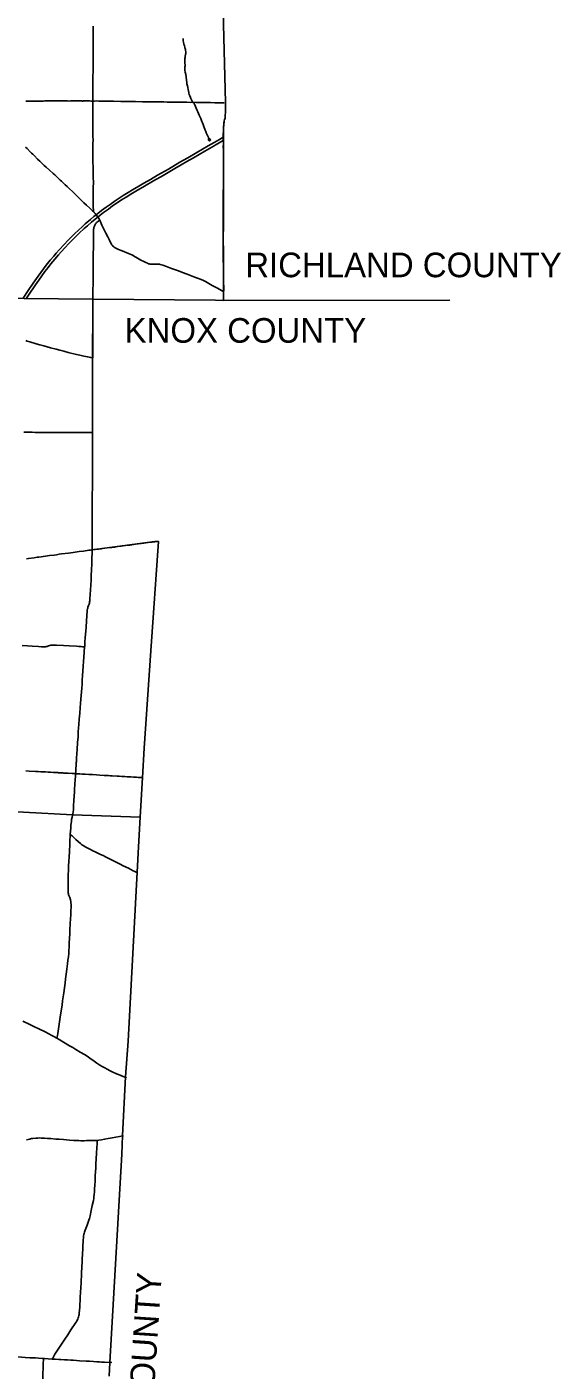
# Model space of a CAD drawing. Extents: x 1815539 to 1947826, y 273303 to 993194.
# Drawn here: x 1926135 to 1947826, y 885394 to 939932 of the extents above; entities that cross this region are included whole.
import ezdxf

# ---------------------------------------------------------------- set-up
doc = ezdxf.new("R2010")
doc.units = 0
for name, color, linetype in [('GM_X_Adjacent_County_Text', 7, 'Continuous'), ('GM_X_County', 7, 'Continuous'), ('GM_X_County_Road', 7, 'Continuous'), ('GM_X_Interstate_Route', 7, 'Continuous'), ('GM_X_State_Route', 7, 'Continuous'), ('GM_X_Township', 7, 'Continuous'), ('GM_X_Township_Road', 7, 'Continuous'), ('PV_X_EOP', 7, 'Continuous')]:
    doc.layers.add(name, color=color, linetype=linetype)

msp = doc.modelspace()

# ---------------------------------------------------------------- linework, layer by layer
at = {"layer": 'GM_X_County'}
msp.add_lwpolyline([(1934067, 942157), (1934195, 936859), (1934202, 936590), (1934187, 936214), (1934165, 936177), (1934141, 936112), (1934134, 936040), (1934113, 935746), (1934115, 935394), (1934114, 935137), (1934107, 931513), (1934121, 929197), (1934122, 928828), (1933789, 928831), (1928810, 928882), (1928810, 928443), (1928806, 926508), (1928802, 923466), (1928787, 918701), (1931337, 919032), (1931473, 919044), (1931168, 914595), (1930891, 910644), (1930824, 909461), (1930733, 907844), (1930665, 906634), (1930611, 905616), (1930247, 898751), (1930144, 897297), (1930019, 894924), (1929994, 894165), (1929509, 885709), (1929483, 885147)], dxfattribs=at)
at = {"layer": 'GM_X_County_Road'}
for points in [[(1928857, 932416), (1928853, 932423), (1928846, 932439), (1928840, 932455), (1928837, 932472), (1928834, 932505), (1928831, 932603), (1928831, 932686), (1928832, 932784), (1928829, 932882), (1928822, 933046), (1928822, 933128), (1928824, 933211), (1928828, 933342), (1928829, 933406), (1928834, 933615), (1928835, 933681), (1928833, 933763), (1928824, 933910), (1928824, 933976), (1928824, 934058), (1928826, 934156), (1928824, 934287), (1928820, 934402), (1928819, 934517), (1928816, 934697), (1928816, 934798), (1928818, 934944), (1928818, 935027), (1928819, 935173), (1928821, 935370), (1928820, 935452), (1928817, 935615), (1928816, 935697), (1928816, 935812), (1928817, 935878), (1928818, 935927), (1928816, 936057), (1928817, 936106), (1928815, 936187), (1928814, 936253), (1928815, 936338), (1928814, 936398), (1928814, 936484), (1928814, 936548), (1928813, 936617), (1928815, 936711), (1928813, 936793), (1928811, 936857), (1928812, 936921)], [(1928817, 928861), (1928819, 929108), (1928819, 929239), (1928821, 929519), (1928823, 929666), (1928824, 929814), (1928825, 929978), (1928826, 930076), (1928827, 930158), (1928827, 930289), (1928828, 930437), (1928830, 930617), (1928832, 930781), (1928834, 930912), (1928835, 931043), (1928837, 931207), (1928836, 931372), (1928836, 931470), (1928838, 931602), (1928841, 931667), (1928845, 931717), (1928849, 931750), (1928856, 931782), (1928865, 931814), (1928877, 931845), (1928890, 931875), (1928907, 931904), (1928926, 931932), (1928946, 931958), (1928968, 931983), (1928992, 932006), (1929016, 932028), (1929041, 932048), (1929055, 932059), (1929067, 932068), (1929077, 932076), (1929084, 932092)], [(1929084, 932092), (1929079, 932103), (1929073, 932118), (1929066, 932132), (1929040, 932173), (1929014, 932209), (1929002, 932227), (1928946, 932299), (1928902, 932357), (1928871, 932395), (1928861, 932409), (1928857, 932416)], [(1928807, 926493), (1928809, 926621), (1928809, 926752), (1928812, 926899), (1928813, 926997), (1928812, 927177), (1928812, 927324), (1928811, 927487), (1928811, 927749), (1928813, 927847), (1928813, 928059), (1928812, 928190), (1928814, 928353), (1928815, 928468), (1928815, 928598), (1928816, 928761), (1928817, 928861)], [(1926090, 927194), (1926151, 927172), (1926261, 927138), (1926513, 927065), (1926655, 927025), (1926829, 926978), (1926956, 926945), (1927098, 926906), (1927320, 926845), (1927478, 926804), (1927637, 926763), (1927811, 926716), (1928145, 926630), (1928289, 926597), (1928449, 926564), (1928610, 926534), (1928723, 926513), (1928807, 926493)], [(1928786, 918696), (1928859, 918706), (1928908, 918712), (1928973, 918721), (1929054, 918732), (1929151, 918744), (1929199, 918750), (1929489, 918787), (1929586, 918799), (1929700, 918813), (1929814, 918828), (1929960, 918847), (1930139, 918870), (1930317, 918893), (1930545, 918924), (1930886, 918970), (1931065, 918992), (1931227, 919011), (1931335, 919024)], [(1931335, 919024), (1931443, 919037)], [(1926118, 918334), (1926198, 918346), (1926425, 918377), (1926555, 918395), (1926620, 918404), (1926896, 918441), (1927059, 918463), (1927237, 918487), (1927335, 918501), (1927448, 918517), (1927546, 918531), (1927822, 918568), (1928017, 918594), (1928261, 918627), (1928439, 918650), (1928654, 918679), (1928720, 918688), (1928786, 918696)], [(1926097, 909720), (1926228, 909714), (1926490, 909698), (1926588, 909693), (1926702, 909687), (1926784, 909684), (1926898, 909680), (1926996, 909675), (1927094, 909669), (1927223, 909662), (1927270, 909659), (1927305, 909657), (1927346, 909654), (1927391, 909652), (1927420, 909650), (1927464, 909647), (1927502, 909645), (1927550, 909642), (1927602, 909639), (1927632, 909637), (1927662, 909636), (1927708, 909633), (1927749, 909630), (1927785, 909628), (1927815, 909626), (1927979, 909618), (1928077, 909613), (1928111, 909611)], [(1928111, 909611), (1928158, 909609), (1928289, 909601), (1928387, 909594), (1928502, 909587), (1928649, 909580), (1928714, 909577), (1928796, 909572), (1928960, 909561), (1929091, 909553), (1929270, 909541), (1929447, 909531), (1929512, 909527), (1929594, 909522), (1929806, 909511), (1929887, 909506), (1929986, 909499), (1930116, 909490), (1930214, 909485), (1930361, 909477), (1930459, 909472), (1930590, 909465), (1930655, 909461), (1930754, 909453), (1930800, 909450), (1930838, 909448)], [(1926124, 894738), (1926250, 894775), (1926282, 894783), (1926330, 894793), (1926378, 894800), (1926493, 894812), (1926575, 894818), (1926657, 894820), (1926722, 894818), (1926853, 894812), (1926968, 894804), (1927115, 894792), (1927311, 894776), (1927442, 894766), (1927622, 894754), (1927867, 894734), (1928047, 894722), (1928162, 894715), (1928244, 894711), (1928326, 894710), (1928457, 894710), (1928555, 894711), (1928834, 894712), (1928933, 894714), (1928990, 894718)], [(1928990, 894718), (1928998, 894718), (1929063, 894726), (1929161, 894741), (1929290, 894765), (1929435, 894792), (1929596, 894823), (1929902, 894884), (1930012, 894908), (1930062, 894919)], [(1924086, 886021), (1924152, 886017), (1924272, 886010), (1924432, 886001), (1924559, 885995), (1924725, 885985), (1924898, 885976), (1924992, 885971), (1925178, 885959), (1925374, 885950), (1925473, 885944), (1925636, 885935), (1925767, 885928), (1926060, 885911), (1926257, 885899), (1926486, 885887), (1926601, 885879), (1926765, 885870), (1926812, 885867)], [(1926681, 883336), (1926686, 883438), (1926691, 883519), (1926703, 883715), (1926716, 883928), (1926732, 884197), (1926739, 884331), (1926751, 884567), (1926761, 884730), (1926769, 884861), (1926777, 885025), (1926781, 885151), (1926786, 885287), (1926792, 885451), (1926798, 885599), (1926802, 885697), (1926807, 885779), (1926811, 885855), (1926812, 885867)], [(1926812, 885867), (1926846, 885865), (1926994, 885854), (1927157, 885843)], [(1927157, 885843), (1927288, 885835), (1927435, 885826), (1927517, 885821), (1927657, 885814), (1927789, 885807), (1927919, 885800), (1928009, 885794), (1928153, 885786), (1928270, 885778), (1928545, 885762), (1928678, 885753), (1928842, 885744), (1928973, 885736), (1929087, 885728), (1929169, 885722), (1929283, 885715), (1929581, 885699)]]:
    msp.add_lwpolyline(points, dxfattribs=at)
at = {"layer": 'GM_X_Interstate_Route'}
for points in [[(1925984, 928918), (1926192, 929225), (1926395, 929523), (1926591, 929807), (1926696, 929953), (1926813, 930111), (1926924, 930254), (1927088, 930459), (1927224, 930623), (1927330, 930748), (1927450, 930882), (1927650, 931100), (1927796, 931255), (1927934, 931395), (1928075, 931533), (1928241, 931691), (1928362, 931802), (1928509, 931933), (1928721, 932115), (1928859, 932230), (1928946, 932299), (1929013, 932353), (1929169, 932474), (1929353, 932611), (1929512, 932726), (1929715, 932866), (1929878, 932975), (1930044, 933081), (1930253, 933211), (1930422, 933312), (1930678, 933459), (1930890, 933583), (1931160, 933740), (1931443, 933905), (1931883, 934160), (1932351, 934432), (1932664, 934614), (1933033, 934827), (1933501, 935100), (1933856, 935305), (1933956, 935362), (1934109, 935451)], [(1932397, 934328), (1932628, 934462), (1932898, 934618), (1933365, 934892), (1933740, 935107)], [(1933740, 935107), (1933777, 935129), (1934110, 935322)], [(1926120, 928917), (1926205, 929042), (1926490, 929464), (1926620, 929653), (1926743, 929827), (1926870, 929999), (1926999, 930168), (1927112, 930310), (1927268, 930500), (1927416, 930675), (1927525, 930798), (1927691, 930980), (1927837, 931135), (1927975, 931276), (1928127, 931426), (1928258, 931551), (1928463, 931740), (1928597, 931860), (1928759, 932000), (1928910, 932126), (1929014, 932209), (1929115, 932290), (1929245, 932390), (1929443, 932537), (1929616, 932661), (1929805, 932792), (1929983, 932909), (1930163, 933024), (1930358, 933144), (1930556, 933261), (1930911, 933466), (1931280, 933680), (1931663, 933902), (1932145, 934183), (1932397, 934328)]]:
    msp.add_lwpolyline(points, dxfattribs=at)
at = {"layer": 'GM_X_State_Route'}
msp.add_lwpolyline([(1925970, 899560), (1926251, 899426), (1926444, 899335), (1926622, 899250), (1926872, 899129), (1927033, 899047), (1927120, 899000), (1927234, 898936), (1927353, 898868), (1927444, 898813), (1927628, 898706), (1927869, 898566), (1927996, 898492), (1928123, 898417), (1928306, 898308), (1928474, 898206), (1928585, 898135), (1928693, 898062), (1928866, 897938), (1928974, 897862), (1929097, 897780), (1929194, 897720), (1929294, 897662), (1929395, 897607), (1929511, 897547), (1929630, 897491), (1929750, 897438), (1929780, 897425), (1929856, 897393), (1930039, 897321), (1930185, 897266)], dxfattribs=at)
at = {"layer": 'GM_X_Township'}
for points in [[(1928810, 928882), (1926026, 928906), (1923489, 928928), (1923428, 928941), (1920005, 929002), (1917092, 929034), (1915316, 929031)], [(1930733, 907844), (1927982, 907939), (1924001, 908161), (1918864, 908449), (1913461, 908761), (1908659, 909041), (1907683, 909106), (1907386, 909123), (1907188, 909134), (1903661, 909327), (1903767, 911000), (1903873, 912675), (1904049, 915466), (1901695, 915145), (1901024, 915054), (1891076, 913698), (1890078, 913562), (1889943, 913553), (1889411, 913481)]]:
    msp.add_lwpolyline(points, dxfattribs=at)
at = {"layer": 'GM_X_Township_Road'}
for points in [[(1928812, 936921), (1928812, 937110), (1928812, 937196), (1928811, 937280), (1928813, 937473), (1928815, 937603), (1928817, 937683), (1928819, 937798), (1928819, 937863), (1928820, 937978), (1928821, 938060), (1928822, 938174), (1928824, 938437), (1928827, 938633), (1928827, 938765), (1928827, 938912), (1928828, 939093), (1928830, 939322), (1928832, 939502), (1928830, 939649), (1928829, 939845), (1928829, 939960)], [(1932885, 936869), (1932856, 936899), (1932841, 936920), (1932819, 936963), (1932793, 937024), (1932774, 937069), (1932750, 937130), (1932729, 937192), (1932715, 937240), (1932707, 937271), (1932683, 937383), (1932668, 937464), (1932652, 937544), (1932636, 937625), (1932625, 937689), (1932616, 937754), (1932597, 937901), (1932583, 937998), (1932566, 938095), (1932554, 938175), (1932549, 938209), (1932549, 938227), (1932549, 938250), (1932555, 938306), (1932560, 938356), (1932562, 938388), (1932560, 938420), (1932555, 938435), (1932545, 938496), (1932544, 938546), (1932545, 938578), (1932547, 938595), (1932550, 938644), (1932556, 938693), (1932564, 938741), (1932576, 938806), (1932584, 938854), (1932586, 938887), (1932586, 938920), (1932582, 938969), (1932577, 939002), (1932574, 939018), (1932565, 939049), (1932554, 939080), (1932543, 939111), (1932529, 939158), (1932516, 939205), (1932509, 939236), (1932490, 939314), (1932481, 939362), (1932478, 939394), (1932477, 939426), (1932479, 939458)], [(1926094, 936918), (1926175, 936920), (1926240, 936920), (1926289, 936919), (1926354, 936920), (1926484, 936922), (1926517, 936922), (1926582, 936922), (1926614, 936921), (1926695, 936921), (1926761, 936922), (1926810, 936922), (1926858, 936923), (1926924, 936925), (1926989, 936925), (1927153, 936926), (1927234, 936927), (1927316, 936928), (1927398, 936928), (1927627, 936925), (1927708, 936925), (1927791, 936923), (1927840, 936922), (1927905, 936924), (1927970, 936924), (1928003, 936925), (1928051, 936926), (1928083, 936926), (1928152, 936925), (1928252, 936926), (1928323, 936925), (1928353, 936924), (1928366, 936923), (1928391, 936922), (1928402, 936922), (1928428, 936923), (1928484, 936925), (1928605, 936925), (1928679, 936924), (1928749, 936922), (1928798, 936920), (1928812, 936921)], [(1928812, 936921), (1928880, 936922), (1928945, 936923), (1929060, 936921), (1929142, 936919), (1929224, 936918), (1929437, 936914), (1929650, 936911), (1929945, 936906), (1930076, 936904), (1930174, 936903), (1930338, 936900), (1930551, 936897), (1930830, 936892), (1931092, 936888), (1931305, 936885), (1931436, 936885), (1931567, 936884), (1931698, 936883), (1931829, 936881), (1931960, 936880), (1932156, 936879), (1932254, 936877), (1932385, 936874), (1932631, 936869), (1932762, 936868), (1932885, 936869)], [(1933514, 935398), (1933514, 935372), (1933513, 935356), (1933514, 935339), (1933516, 935331), (1933519, 935324), (1933525, 935318), (1933531, 935312), (1933541, 935308), (1933551, 935306), (1933560, 935307), (1933567, 935309), (1933574, 935312), (1933579, 935318), (1933583, 935323), (1933586, 935331), (1933587, 935339), (1933586, 935347), (1933583, 935354), (1933574, 935368), (1933564, 935381), (1933539, 935402), (1933527, 935414), (1933517, 935426), (1933509, 935440), (1933501, 935454), (1933494, 935467), (1933480, 935495), (1933467, 935524), (1933453, 935553), (1933433, 935598), (1933420, 935628), (1933413, 935643), (1933395, 935688), (1933378, 935734), (1933361, 935780), (1933338, 935842), (1933292, 935963), (1933262, 936039), (1933244, 936085), (1933194, 936206), (1933136, 936342), (1933076, 936477), (1933049, 936537), (1933009, 936627), (1932975, 936702), (1932935, 936792), (1932921, 936822), (1932913, 936836), (1932905, 936849), (1932885, 936869)], [(1932885, 936869), (1933007, 936867), (1933089, 936865), (1933204, 936862), (1933302, 936859), (1933482, 936858), (1933531, 936857), (1933597, 936857), (1933760, 936854), (1933859, 936852), (1934148, 936848)], [(1934112, 935125), (1934113, 935200), (1934110, 935322), (1934108, 935381), (1934109, 935451), (1934110, 935576), (1934117, 935708), (1934123, 935873), (1934130, 935975), (1934142, 936067), (1934148, 936099)], [(1926084, 935050), (1926142, 934993), (1926269, 934865), (1926327, 934808), (1926374, 934762), (1926443, 934692), (1926570, 934565), (1926663, 934473), (1926735, 934406), (1926844, 934307), (1926916, 934241), (1927048, 934118), (1927206, 933975), (1927267, 933920), (1927338, 933853), (1927446, 933752), (1927493, 933707), (1927541, 933662), (1927613, 933596), (1927697, 933518), (1927767, 933449), (1927848, 933369), (1927999, 933231), (1928119, 933116), (1928210, 933031), (1928454, 932793), (1928560, 932691), (1928690, 932566), (1928803, 932459), (1928857, 932416)], [(1934109, 931509), (1934109, 931531), (1934112, 931695), (1934112, 931826), (1934115, 932039), (1934117, 932138), (1934118, 932203), (1934117, 932433), (1934117, 932597), (1934116, 932728), (1934115, 932826), (1934116, 932907), (1934116, 933104), (1934116, 933186), (1934117, 933301), (1934117, 933448), (1934116, 933596), (1934116, 933678), (1934116, 933792), (1934117, 933890), (1934117, 933972), (1934117, 934070), (1934118, 934168), (1934118, 934233), (1934115, 934598), (1934114, 934790), (1934114, 934914), (1934111, 935082), (1934112, 935125)], [(1929084, 932092), (1929108, 932051), (1929149, 931947), (1929174, 931886), (1929201, 931827), (1929231, 931768), (1929303, 931639), (1929348, 931552), (1929420, 931405), (1929485, 931273), (1929545, 931156), (1929569, 931113), (1929587, 931086), (1929607, 931060), (1929628, 931035), (1929651, 931012), (1929677, 930991), (1929717, 930963), (1929745, 930947), (1929775, 930932), (1929850, 930899), (1930002, 930838), (1930259, 930732), (1930395, 930674), (1930454, 930646), (1930511, 930614), (1930566, 930578), (1930622, 930545), (1930765, 930465), (1930881, 930404), (1930970, 930361), (1931029, 930334), (1931075, 930316), (1931107, 930307), (1931139, 930301), (1931171, 930297), (1931220, 930295), (1931319, 930298), (1931434, 930301), (1931483, 930300), (1931515, 930296), (1931547, 930290), (1931595, 930277), (1931657, 930257), (1931811, 930201), (1932010, 930125), (1932209, 930049), (1932286, 930020), (1932454, 929957), (1932639, 929889), (1932777, 929838), (1932915, 929785), (1933022, 929744), (1933098, 929715), (1933175, 929686), (1933281, 929643), (1933311, 929629), (1933383, 929591), (1933526, 929510), (1933654, 929437), (1933842, 929336), (1933970, 929264), (1934043, 929226), (1934118, 929190)], [(1934118, 929190), (1934123, 929206), (1934126, 929223), (1934127, 929256), (1934128, 929354), (1934127, 929419), (1934125, 929501), (1934123, 929599), (1934121, 929746), (1934119, 929943), (1934117, 930090), (1934116, 930253), (1934115, 930401), (1934116, 930515), (1934116, 930646), (1934115, 930793), (1934114, 930907), (1934111, 931201), (1934110, 931332), (1934109, 931447), (1934109, 931509)], [(1926011, 923474), (1926192, 923471), (1926356, 923471), (1926471, 923469), (1926733, 923469), (1926848, 923469), (1927062, 923467), (1927193, 923466), (1927289, 923467), (1927487, 923465), (1927572, 923464), (1927635, 923464), (1927717, 923464), (1927831, 923464), (1927979, 923462), (1928143, 923460), (1928241, 923460), (1928340, 923461), (1928454, 923461), (1928585, 923460), (1928779, 923458)], [(1928479, 914761), (1928482, 914800), (1928495, 914980), (1928504, 915111), (1928516, 915291), (1928524, 915389), (1928538, 915569), (1928569, 916027), (1928582, 916207), (1928588, 916256), (1928596, 916304), (1928605, 916336), (1928615, 916367), (1928644, 916444), (1928660, 916490), (1928674, 916537), (1928684, 916586), (1928690, 916634), (1928696, 916700), (1928709, 916913), (1928717, 917044), (1928731, 917289), (1928740, 917453), (1928752, 917682), (1928759, 917862), (1928769, 918157), (1928775, 918321), (1928784, 918600), (1928786, 918696)], [(1925943, 914812), (1926156, 914799), (1926352, 914787), (1926614, 914768), (1926729, 914762), (1926811, 914761), (1926860, 914762), (1926892, 914766), (1926925, 914771), (1926956, 914779), (1927019, 914798), (1927067, 914812), (1927115, 914822), (1927163, 914829), (1927212, 914833), (1927262, 914834), (1927344, 914831), (1927622, 914815), (1927851, 914798), (1928146, 914781), (1928244, 914775), (1928342, 914768), (1928391, 914765), (1928423, 914764), (1928453, 914762), (1928479, 914761)], [(1928111, 909611), (1928118, 909691), (1928122, 909730), (1928125, 909770), (1928129, 909854), (1928134, 909920), (1928137, 909984), (1928141, 910028), (1928143, 910062), (1928145, 910109), (1928147, 910131), (1928149, 910157), (1928150, 910172), (1928154, 910236), (1928167, 910433), (1928179, 910597), (1928196, 910875), (1928212, 911104), (1928224, 911317), (1928237, 911464), (1928249, 911627), (1928263, 911807), (1928274, 911954), (1928282, 912053), (1928301, 912298), (1928314, 912461), (1928327, 912641), (1928339, 912788), (1928361, 913082), (1928374, 913246), (1928384, 913410), (1928396, 913590), (1928423, 913966), (1928438, 914178), (1928449, 914326), (1928464, 914555), (1928479, 914761)], [(1928004, 907983), (1928019, 908068), (1928026, 908149), (1928035, 908336), (1928044, 908498), (1928056, 908728), (1928063, 908842), (1928072, 908973), (1928085, 909187), (1928097, 909368), (1928105, 909502), (1928110, 909585), (1928111, 909611)], [(1927900, 907146), (1927910, 907290), (1927916, 907388), (1927926, 907502), (1927945, 907681), (1927954, 907747), (1927972, 907844), (1928004, 907983)], [(1927353, 898868), (1927378, 898982), (1927392, 899062), (1927447, 899435), (1927491, 899727), (1927541, 900067), (1927562, 900213), (1927588, 900392), (1927632, 900717), (1927658, 900912), (1927684, 901107), (1927708, 901286), (1927730, 901465), (1927758, 901676), (1927785, 901887), (1927805, 902034), (1927822, 902180), (1927834, 902311), (1927841, 902409), (1927850, 902589), (1927858, 902753), (1927866, 902900), (1927875, 903129), (1927886, 903330), (1927892, 903462), (1927897, 903554), (1927905, 903684), (1927919, 903911), (1927923, 903977), (1927927, 904063), (1927931, 904173), (1927934, 904233), (1927933, 904295), (1927926, 904370), (1927917, 904420), (1927904, 904484), (1927874, 904577), (1927850, 904640), (1927830, 904694), (1927820, 904731), (1927815, 904770), (1927812, 904796), (1927810, 904822), (1927808, 904861), (1927807, 904907), (1927806, 904949), (1927807, 905113), (1927812, 905424), (1927815, 905539), (1927819, 905654), (1927827, 905857), (1927837, 906063), (1927847, 906227), (1927861, 906456), (1927877, 906751), (1927885, 906915), (1927895, 907078), (1927900, 907146)], [(1927900, 907146), (1927935, 907116), (1927972, 907084), (1928126, 906937), (1928235, 906837), (1928309, 906772), (1928360, 906731), (1928400, 906703), (1928442, 906677), (1928499, 906645), (1928616, 906586), (1928748, 906520), (1928820, 906482), (1928908, 906439), (1928996, 906395), (1929099, 906347), (1929128, 906333), (1929231, 906284), (1929333, 906233), (1929435, 906181), (1929597, 906102), (1929758, 906020), (1929919, 905939), (1930051, 905874), (1930255, 905770), (1930445, 905672), (1930519, 905637), (1930579, 905612), (1930620, 905598)], [(1927157, 885843), (1927183, 885884), (1927277, 886038), (1927357, 886162), (1927438, 886285), (1927545, 886450), (1927681, 886656), (1927799, 886833), (1927927, 887024), (1928126, 887325), (1928161, 887381), (1928184, 887423), (1928206, 887468), (1928223, 887514), (1928237, 887561), (1928248, 887609), (1928255, 887657), (1928263, 887723), (1928271, 887821), (1928280, 887968), (1928288, 888083), (1928295, 888197), (1928304, 888344), (1928319, 888557), (1928330, 888737), (1928341, 888950), (1928346, 889048), (1928353, 889212), (1928359, 889327), (1928371, 889589), (1928381, 889786), (1928387, 889933), (1928393, 890064), (1928398, 890146), (1928404, 890293), (1928408, 890392), (1928427, 890670), (1928434, 890785), (1928441, 890850), (1928449, 890898), (1928460, 890946), (1928474, 890993), (1928501, 891071), (1928554, 891209), (1928583, 891285), (1928629, 891408), (1928654, 891486), (1928672, 891549), (1928699, 891661), (1928746, 891869), (1928792, 892077), (1928836, 892286), (1928851, 892366), (1928860, 892431), (1928870, 892529), (1928877, 892627), (1928887, 892758), (1928894, 892905), (1928902, 893069), (1928907, 893151), (1928913, 893298), (1928920, 893446), (1928930, 893593), (1928937, 893724), (1928952, 894019), (1928960, 894166), (1928965, 894264), (1928971, 894346), (1928974, 894411), (1928985, 894590), (1928988, 894655), (1928989, 894672), (1928990, 894718)]]:
    msp.add_lwpolyline(points, dxfattribs=at)
at = {"layer": 'PV_X_EOP'}
msp.add_line((1934122, 928828), (1943305, 928835), dxfattribs=at)

# ---------------------------------------------------------------- texts
at = {"layer": 'GM_X_Adjacent_County_Text'}
for s, p in [('RICHLAND COUNTY', (1935002, 929767)), ('KNOX COUNTY', (1930105, 927108))]:
    msp.add_text(s, height=1000, dxfattribs=at).set_placement(p)
msp.add_text('KNOX COUNTY', height=1000, rotation=86.2231, dxfattribs=at).set_placement((1930970, 879537))

doc.saveas('drawing.dxf')
